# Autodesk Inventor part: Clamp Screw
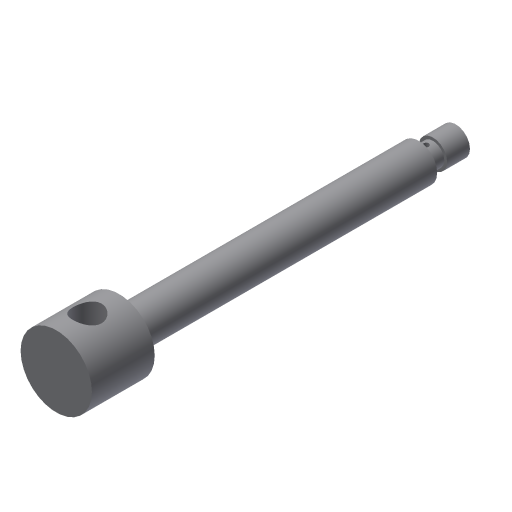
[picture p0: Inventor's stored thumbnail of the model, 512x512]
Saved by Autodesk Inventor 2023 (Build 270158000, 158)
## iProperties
Shininess: 77.0
Length Units: 11269
Angle Units: 11279
Time Units: 11290
Mass Units: 11283
Length Display Precision: 3
Angle Display Precision: 2
Created: 2002-02
Part Number: Clamp Screw
Document SubType Name: Modeling
Designer: ***
Density: 1 g/cm^3
Material: Generic
Mass: 23.4191 g
Surface Area: 81.8482 cm^2
Volume: 23.4191 cm^3
Appearance: Default
Density: 0.0
Volumn: 0.0
Area: 0.0
PropertySet Name: Model Information
Control State: 0
Master: False
Checked Out: False
Author: ***
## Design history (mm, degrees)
sketch "Sketch1"
  geometry: L1 (0, 140)-(5, 140); L2 (5, 140)-(5, 132); L3 (5, 132)-(4, 132); L4 (4, 132)-(4, 127); L5 (4, 127)-(6.5, 127); L6 (6.5, 127)-(6.5, 25); L7 (6.5, 25)-(4, 25); L8 (4, 25)-(4, 22); L9 (4, 22)-(12.5, 22); L10 (12.5, 22)-(12.5, 0); L11 (12.5, 0)-(0, 0); L12 (0, 0)-(0, 140)
  constraints: 24 end point, 10 parallel, 1 horizontal, 1 perpendicular
  dimensions: "d0" = 10 diameter of L2 L12; "d1" = 8 diameter of L4 L12; "d2" = 13 diameter of L6 L12; "d3" = 8 diameter of L7.end L12; "d4" = 25 diameter of L10 L12; "d5" = 3 distance from line of L7.end L9; "d6" = 8 distance of L1.end L2.end; "d7" = 13 vertical distance of L1.end L5.end; "d8" = 22 distance of L9.end L10.end; "d10" = 102 distance of L5.end L6.end
revolve "Revolution1" sketch "Sketch1" stored, may be unused: angle "d11" = 90 deg
sketch "Sketch3"
  geometry: L1 (-12.5, 0)-(12.5, 0) reference; C1 r 5 at (-0.113, 11)
  constraints: 1 centre point
  dimensions: "d13" = 10 diameter of C1; "d14" = 11 distance from line of L1 C1.centre
extrude "Extrusion1" cut sketch "Sketch3" extent not by distance; stored distance "d15" = 10; taper "d16" = 0 deg
sketch "Sketch4"
  geometry: L1 (0, 138.841)-(0, 0); L2 (-12.5, 0)-(12.5, 0) reference; L3 (-5, 140)-(5, 140) reference; C1 r 1 at (0, 129.5)
  constraints: 2 end point, 1 centre point, 1 point on line, 1 vertical
  dimensions: "d17" = 2 diameter of C1; "d18" = 10.5 distance from line of L3 C1.centre
extrude "Extrusion2" cut sketch "Sketch4" stored distance "d19" = 10; taper "d20" = 0 deg
body "Solid1"
